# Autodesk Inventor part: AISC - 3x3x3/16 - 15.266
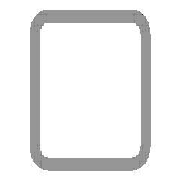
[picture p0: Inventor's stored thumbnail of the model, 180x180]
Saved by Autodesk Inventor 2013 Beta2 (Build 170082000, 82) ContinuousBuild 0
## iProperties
_CCFamilyMember: 9
_CCFamilyDisplayName: ANSI AISC (Square) - Tube
_FrameMemberDoc: Frame Member File
_Version: 15.0.0
_GetPNFromCC: 1
Created: 2011-01
Part Number: AISC - 3x3x3/16 - 15.266
Material: Steel, Mild
Description: Tube
Document SubType Name: Modeling
Standard: ANSI
Designer: Beta-8540w
Standards Organization: ANSI
Language: en-US
Size Designation: 3x3x3/16
Categories: <MemberInstance><Categories><Category DisplayName="Structural Shapes" InternalName="089c4875-fa83-4c05-b084-43b9cc11f5ed" Mnemonic="GRDR"><CategoryParameter Dis
Stock Number: 3x3x3/16
Density: 7.86 g/cm^3
IsCustomPart: 1
G_L: 15.266 in
G_W: 3.000 in
G_H: 3.000 in
+97117C38-DCE9-4757-BAD2-BD9438CA5631+CUTDETAIL1: Cut
+82DD3A4A-9495-4CA2-B707-475D0CBCAB53+CUTDETAIL2: Cut
Author: Beta-8540w
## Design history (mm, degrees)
node "Start plane"
node "End plane"
sketch "Sketch"
  geometry: L1 (-38.1, -28.575)-(-38.1, 28.575); L2 (-28.575, 38.1)-(28.575, 38.1); L3 (38.1, 28.575)-(38.1, -28.575); L4 (28.575, -38.1)-(-28.575, -38.1); L5 (-28.575, 33.337)-(28.575, 33.338); L6 (33.338, 28.575)-(33.338, -28.575); L7 (28.575, -33.337)-(-28.575, -33.338); L8 (-33.338, -28.575)-(-33.338, 28.575); L9 (0, 56.102)-(0, -56.102) reference; L10 (-56.102, 0)-(56.102, 0) reference; A1 r 9.525 centre (-28.575, -28.575) between (-38.1, -28.575) and (-28.575, -38.1); A2 r 9.525 centre (-28.575, 28.575) between (-28.575, 38.1) and (-38.1, 28.575); A3 r 9.525 centre (28.575, 28.575) between (38.1, 28.575) and (28.575, 38.1); A4 r 9.525 centre (28.575, -28.575) between (28.575, -38.1) and (38.1, -28.575); A5 r 4.763 centre (-28.575, 28.575) between (-28.575, 33.337) and (-33.338, 28.575); A6 r 4.763 centre (28.575, 28.575) between (33.338, 28.575) and (28.575, 33.338); A7 r 4.763 centre (28.575, -28.575) between (28.575, -33.337) and (33.338, -28.575); A8 r 4.763 centre (-28.575, -28.575) between (-33.338, -28.575) and (-28.575, -33.338)
  constraints: 16 end point, 16 point on circle, 8 centre point, 8 tangent, 4 parallel, 3 equal radius, 2 perpendicular, 7 other
  dimensions: "d10" = 76.2 distance between parallel lines of L2 L4 (= G_H); "d11" = 76.2 distance between parallel lines of L1 L3 (= G_W); "d12" = 4.7625 distance between parallel lines of L3 L6 (= G_T); "d15" = 38.1 distance between parallel lines of L2 L10 (= 0.5 x d10); "d16" = 38.1 distance between parallel lines of L9 L3 (= 0.5 x d11); "d17" = 9.525 radius of A1 (= G_IR)
extrude "Body" new body sketch "Sketch" stored distance "d3" = 387.75605 (= G_L); taper "d4" = 0 deg
node "Driven Length"
  sketch "Sketch3"
    geometry: L1 (0, 0)-(10, 0) reference
    constraints: 2 end point, 1 horizontal
  workplane "Work Plane3"
  sketch "Sketch4"
    geometry: L1 (-2, 31.109)-(12, 31.109) reference; L2 (-2, 418.865)-(12, 418.865) reference
    dimensions: "d19" = 387.75605 distance between parallel lines of L1 L2 (derived)
workplane "Work Plane4"
split "Split1"
workplane "Work Plane5"
split "Split2"
body "Solid1"
other parameters: "G_W" = 76.2 [user parameter; used in 1 equation term], "G_H" = 76.2 [user parameter; used in 1 equation term], "G_T" = 4.7625 [user parameter; used in 1 equation term], "G_IR" = 9.525 [user parameter; used in 1 equation term], "G_L" = 387.75605 (= d19) [user parameter; used in 1 equation term], "G_OFFSET_START" = -31.10852 [user parameter; used in 1 equation term], "G_OFFSET_END" = -31.10852 [user parameter; used in 1 equation term], "d13" = 31.10852 (= -G_OFFSET_START), "d14" = 418.86457 (= G_OFFSET_END + B_L), "B_L" = 449.97309 [user parameter; used in 1 equation term], "d18" = 90 deg
